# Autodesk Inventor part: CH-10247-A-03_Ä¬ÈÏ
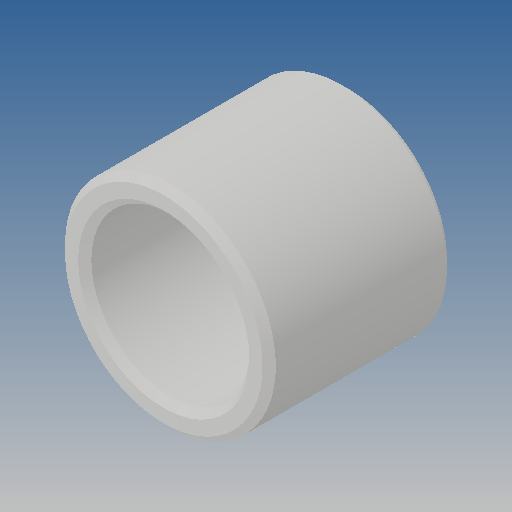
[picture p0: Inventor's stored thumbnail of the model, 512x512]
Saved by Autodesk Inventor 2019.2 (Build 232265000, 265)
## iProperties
Created: 2010-06
Part Number: CH-10247-A-03_Ä¬ÈÏ
Material: Ogólny
Document SubType Name: Modeling
Designer: CADENGINEERING4
Density: 1 g/cm^3
Appearance: Domyślna
Author: CADENGINEERING4
Revision Number: ÈÎºÎ
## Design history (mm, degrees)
feature "NONE"
node "Bryła1"
